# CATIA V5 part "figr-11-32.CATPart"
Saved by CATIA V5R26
Part number: Part1
Bounding box of the stored display mesh (mm): x -280 to 270, y -160 to 10, z 0 to 443
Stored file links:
  D:\_Deepak\CATIA\CATIA V5-6R2016_Deepak\Resources\Part files\Partfiles\c11_catia_v5_6r2016_prt\figr-11-32.CATPart
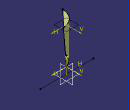
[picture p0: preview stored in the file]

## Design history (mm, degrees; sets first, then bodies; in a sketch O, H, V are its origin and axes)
Set1
  Plane1: type Offset, RefPlane xy-plane, Offset 443
  Sketch1 on Plane1, origin (0, 0, 443), H (1, 0, 0), V (0, 1, 0)
    arc A1 centre (51.3551, -160.9813) radius 171.358 from (40, 10) to (-120, -160) ccw
  Loft1: Sections (Sketch3; Sketch1)
  Sketch2 on zx-plane, origin (0, 0, 0), H (-1, 0, 0), V (0, 0, 1)
    line L1 (-270, 0) -> (280, 0)
    point P1 (-270, 0)
    coincidence: P1 H
    horizontal: L1 H
Body1 (main body)
  Sketch3 on Plane2, origin (0, 0, 67), H (1, 0, 0), V (0, 1, 0)
    point P1 (-100, 0)
    arc A1 centre (50, -150) radius 158.1139 from (0, 0) to (-100, -100) ccw
Set2
  Plane2: type Offset, RefPlane xy-plane, Offset 67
